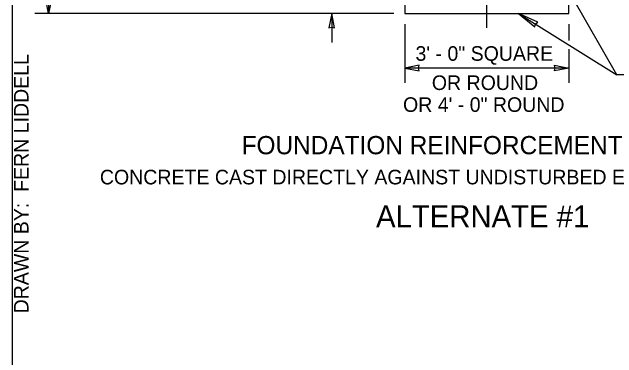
# Model space of a CAD drawing. Extents: x 99862 to 103151, y 100000 to 102076.
# Drawn here: x 99862 to 100525, y 100946 to 101325 of the extents above; entities that cross this region are included whole.
import ezdxf

# ---------------------------------------------------------------- set-up
doc = ezdxf.new("R2010")
doc.units = 0
for name, color, linetype in [('Level 1', 7, 'Continuous'), ('Level 15', 7, 'Continuous'), ('Level 2', 7, 'Continuous'), ('Level 20', 7, 'Continuous'), ('Level 62', 7, 'Continuous')]:
    doc.layers.add(name, color=color, linetype=linetype)

msp = doc.modelspace()

# ---------------------------------------------------------------- linework, layer by layer
at = {"layer": 'Level 1'}
msp.add_lwpolyline([(99862, 99999.5), (103151, 99999.5), (103151, 102075.5), (99862, 102075.5)], close=True, dxfattribs=at)
at = {"layer": 'Level 15'}
for p, q in [((100382.17, 101307.99), (100382.17, 102008.07)), ((99902.04, 101803.99), (99902.04, 101323.99)), ((100524.64, 101256.61), (100472.17, 101348)), ((100280.17, 101323.99), (99887.04, 101323.99)), ((100212.17, 101323.99), (100212.17, 101291.99)), ((100416.93, 101323.99), (100524.64, 101256.61)), ((100292.17, 101311.99), (100292.17, 101247.99)), ((100472.17, 101311.99), (100472.17, 101294.15)), ((100472.17, 101284.71), (100472.17, 101247.99)), ((100472.17, 101263.99), (100292.17, 101263.99)), ((100540.64, 101256.61), (100524.64, 101256.61))]:
    msp.add_line(p, q, dxfattribs=at)
for points in [[(99902.04, 101323.99), (99898.96, 101339.71), (99902.04, 101338.98), (99905.12, 101339.71)], [(100212.17, 101323.99), (100209.09, 101308.26), (100212.17, 101308.99), (100215.25, 101308.26)], [(100416.93, 101323.99), (100434.7, 101309.35), (100435.39, 101312.44), (100437.87, 101314.41)], [(100292.17, 101263.99), (100307.9, 101260.9), (100307.17, 101263.99), (100307.9, 101267.07)], [(100472.17, 101263.99), (100456.45, 101260.9), (100457.17, 101263.99), (100456.45, 101267.07)]]:
    msp.add_lwpolyline(points, close=True, dxfattribs=at)
at = {"layer": 'Level 2'}
for p, q in [((100292.17, 101803.99), (100292.17, 101323.99)), ((100472.17, 101323.99), (100472.17, 101803.99)), ((100292.17, 101323.99), (100472.17, 101323.99))]:
    msp.add_line(p, q, dxfattribs=at)

# ---------------------------------------------------------------- texts
at = {"layer": 'Level 20'}
for s, height, p in [('3\' - 0" SQUARE', 16, (100303.99, 101271.99)), ('OR ROUND', 16, (100321.91, 101239.99)), ('OR 4\' - 0" ROUND', 16, (100290.35, 101215.99)), ('FOUNDATION REINFORCEMENT DETAIL', 20, (100113.45, 101169.57)), ('CONCRETE CAST DIRECTLY AGAINST UNDISTURBED EARTH, DRILLED SHAFT', 16, (99958.18, 101136.57)), ('ALTERNATE #1', 24, (100260.76, 101089.57))]:
    msp.add_text(s, height=height, dxfattribs=at).set_placement(p)
at = {"layer": 'Level 62'}
msp.add_text('DRAWN BY:  FERN LIDDELL', height=16, rotation=90, dxfattribs=at).set_placement((99880, 100995.22))

doc.saveas('drawing.dxf')
